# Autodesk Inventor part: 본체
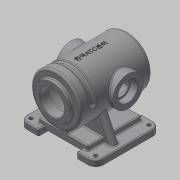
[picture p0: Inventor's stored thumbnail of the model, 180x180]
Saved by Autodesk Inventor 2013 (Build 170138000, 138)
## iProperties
Created: 2015-10
Part Number: 본체
Document SubType Name: Modeling
Designer: mdu
Density: 1 g/cm^3
Material: 알루미늄 6061
Mass: 1694.51 g
Surface Area: 2715.66 cm^2
Volume: 1694.51 cm^3
Author: mdu
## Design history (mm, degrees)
sketch "스케치1"
  geometry: L1 (-100, 85)-(-50, 85); L2 (-50, 85)-(-50, -85); L3 (-50, -85)-(-100, -85); L4 (-100, -85)-(-100, 85); L5 (50, 85)-(100, 85); L6 (100, 85)-(100, -85); L7 (100, -85)-(50, -85); L8 (50, -85)-(50, 85); 3 further points
  constraints: 16 end point, 4 parallel, 2 equal length, 2 horizontal, 2 horizontal alignment, 2 midpoint, 2 perpendicular
  dimensions: "d0" = 100 distance between parallel lines of L8 L2; "d1" = 170 distance of L3.end L1.start; "d3" = 200 distance between parallel lines of L6 L4; "d4" = 50 distance from line of point (0, 0) L2 (= 0.5 x d0)
extrude "돌출1" new body sketch "스케치1" distance "d5" = 16; taper "d6" = 0 deg
node "작업 평면1"
sketch "스케치2"
  geometry: L1 (-65, 70)-(65, 70); L2 (65, 70)-(65, -70); L3 (65, -70)-(-65, -70); L4 (-65, -70)-(-65, 70); 3 further points
  constraints: 8 end point, 2 midpoint, 2 parallel, 1 horizontal, 1 horizontal alignment, 1 perpendicular, 1 vertical alignment
  dimensions: "d8" = 130 distance of L2.end L3.end; "d9" = 140 distance of L1.end L2.end
extrude "돌출2" join sketch "스케치2" distance "d10" = 20; taper "d11" = 0 deg
sketch "스케치3"
  geometry: L1 (-100, 110)-(100, 110); L2 (85, 0)-(-85, 0) reference; L3 (100, 110)-(100, 175); L4 (100, 175)-(-90, 175); L5 (-90, 175)-(-90, 156); L6 (-90, 156)-(-100, 156); L7 (-100, 156)-(-100, 110); L8 (90, 110)-(90, 165); L9 (90, 165)-(-75, 165); L10 (-75, 165)-(-75, 110); L11 (-100, 142.5)-(-75, 142.5); 3 further points
  constraints: 20 end point, 5 perpendicular, 4 parallel, 4 point on line, 2 midpoint, 1 horizontal, 1 vertical alignment
  dimensions: "d12" = 110 distance from line of L2 L1.end; "d13" = 200 distance of L1.start L1.end; "d14" = 130 diameter of L4 L1; "d15" = 92 diameter of L6 L1; "d16" = 10 distance of L5.end L6.end; "d42" = 110 diameter of L9 L1; "d43" = 10 distance between parallel lines of L3 L8; "d44" = 25 distance between parallel lines of L10 L7; "d45" = 65 diameter of L11 L1
revolve "회전1" sketch "스케치3" stored, may be unused: angle "d17" = 90 deg
sketch "스케치4"
  geometry: L1 (-50, 70)-(50, 70) reference; L2 (50, -70)-(-50, -70) reference; L3 (-10, 70)-(-10, -70); L4 (10, -70)-(10, 70); 1 further point
  constraints: 4 end point, 4 point on line, 2 perpendicular
  dimensions: "d18" = 20 distance between parallel lines of L4 L3; "d19" = 10 distance from line of point (0, 0) L3
extrude "돌출3" join sketch "스케치4" stored distance "d20" = 10; taper "d21" = 0 deg
node "작업 평면2"
sketch "스케치5"
  geometry: L1 (-50, -8)-(0, -8) reference; L2 (100, -8)-(150, -8) reference; L3 (-40, -8)-(-8.943, -74.601); L4 (140, -8)-(108.943, -74.601); L5 (-50, 8)-(-50, -8) reference; L6 (150, 8)-(150, -8) reference; A1 r 65 centre (50, -102) between (-8.943, -74.601) and (108.943, -74.601) reference; 1 further point
  constraints: 4 end point, 2 point on circle, 2 point on line, 1 equal length
  dimensions: "d23" = 10 distance from line of L3.start L5; "d24" = 10 distance from line of L4.start L6; "d25" = 25 deg angle of L3 L5
feature "리브1" sketch "스케치5" dims "d26" = 1, "d27" = 20, "d28" = 0
node "작업 평면3"
sketch "스케치6"
  geometry: L1 (100, 156)-(100, 64) reference; C1 r 40 at (-25, 110); 2 further points
  constraints: 1 centre point, 1 horizontal alignment, 1 midpoint
  dimensions: "d37" = 80 diameter of C1; "d38" = 125 distance from line of C1.centre L1
extrude "돌출4" join sketch "스케치6" stored distance "d39" = 10; taper "d40" = 0 deg
hole "구멍1" diameter "d48" = 42; stored, may be unused: countersink angle "d52" = 90 deg, drill point angle "d54" = 118 deg; dims "d46" = 10, "d47" = 10, "d49" = 6, "d50" = 52, "d51" = 18, "d53" = 8
sketch "스케치7"
  geometry: C1 r 40 at (0, 0) reference; 2 further points
  constraints: 1 horizontal alignment
  dimensions: "d55" = 32.5 distance of point (32.5, 0) C1.centre
hole "구멍2" sketch "스케치7" at (32.5, 0) diameter "d56" = 3.242; stored, may be unused: countersink angle "d60" = 90 deg, drill point angle "d62" = 118 deg; dims "d57" = 11, "d58" = 52, "d59" = 18, "d61" = 13
sketch "스케치8"
  geometry: C1 r 46 at (0, 0) reference; 2 further points
  constraints: 1 vertical alignment
  dimensions: "d66" = 39 distance of C1.centre point (0, 39)
hole "구멍3" sketch "스케치8" at (0, 39) diameter "d67" = 3.242; stored, may be unused: countersink angle "d71" = 90 deg, drill point angle "d73" = 118 deg; dims "d68" = 11, "d69" = 52, "d70" = 18, "d72" = 13
fillet "모깎기7" dims "d77" = 20, "d78" = 5, "d79" = 3, "d80" = 10, "d107" = 10
fillet "모깎기8" dims "d81" = 3
fillet "모깎기9" dims "d82" = 3
fillet "모깎기10" dims "d83" = 3, "d84" = 0.3
chamfer "모따기1" distance "d85" = 1; stored, may be unused: second distance "d86" = 2, angle "d87" = 45 deg
node "작업 평면4"
sketch "스케치10"
  geometry: 5 further points
  constraints: 2 horizontal alignment, 2 vertical alignment
  dimensions: "d90" = 170 distance of point (85, 70) point (-85, 70); "d91" = 140 distance of point (-85, 70) point (-85, -70); "d92" = 70 vertical distance of point (0, 0) point (-85, -70) (= 0.5 x d91); "d93" = 85 horizontal distance of point (0, 0) point (-85, 70) (= 0.5 x d90)
hole "구멍4" sketch "스케치10" at (-85, 70), (85, 70), (85, -70), (-85, -70) diameter "d94" = 10; stored, may be unused: countersink angle "d98" = 90 deg, drill point angle "d100" = 118 deg; dims "d95" = 6, "d96" = 4, "d97" = 2, "d99" = 8
node "작업 평면5"
sketch "스케치12" dims "d22" = -90
  geometry: L1 (-65, -90)-(65, -90) reference; L2 (65, 85)-(-65, 85) reference; L3 (0, -90)-(0, 85); 3 further points
  constraints: 3 midpoint, 2 end point, 1 coincident, 1 other
feature "엠보싱3" sketch "스케치12" dims "d105" = 1, "d106" = 0
node "작업축1"
sketch "스케치13"
  geometry: L1 (-85, 175)-(90, 175) reference; L2 (-65, 175)-(-50, 175); L3 (-50, 175)-(-50, 170); L4 (-50, 170)-(-65, 170); L5 (-65, 170)-(-65, 175); L6 (-90, 50)-(-90, 170) reference; L7 (-140, 110)-(140, 110) reference; 1 further point
  constraints: 8 end point, 2 parallel, 1 horizontal, 1 perpendicular, 1 point on line
  dimensions: "d108" = 25 distance between parallel lines of L5 L6; "d109" = 15 distance of L3.end L4.end; "d110" = 5 distance of L2.end L3.end
revolve "회전2" sketch "스케치13" stored, may be unused: angle "d111" = 180 deg
fillet "모깎기11" dims "d112" = 5
fillet "모깎기12" dims "d113" = 5
fillet "모깎기13" dims "d114" = 3
node "솔리드1"
mirror "대칭1"
pattern_circular "원형 패턴1" dims angle "d64" = 360 deg
mirror "대칭3"
pattern_circular "원형 패턴2" dims angle "d75" = 360 deg
other parameters: "d7" = 8, "d36" = -75
